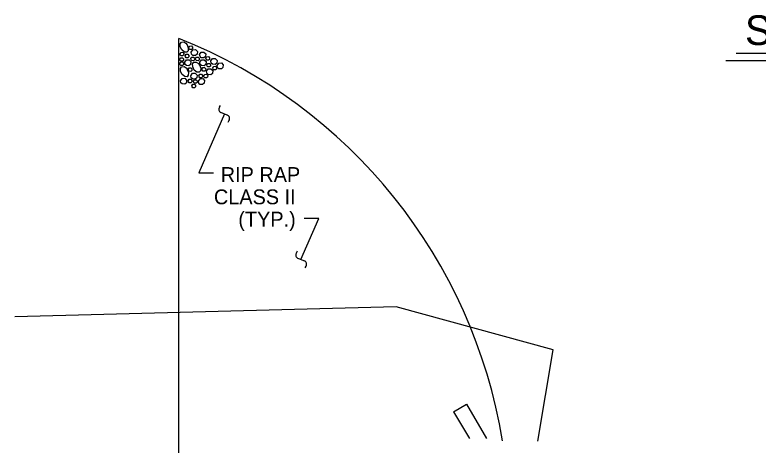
# Model space of a CAD drawing. Extents: x 985 to 1514, y -701 to -21.
# Drawn here: x 1052.9 to 1102.9, y -135.8 to -106.8 of the extents above; entities that cross this region are included whole.
import ezdxf

# ---------------------------------------------------------------- set-up
doc = ezdxf.new("R2010")
doc.units = 0
for name, color, linetype in [('Arrowhead Terminators CELL', 7, 'Continuous'), ('Dimension Lines', 7, 'Continuous'), ('Exist Hydro Stream or Body of Water', 7, 'Continuous'), ('Exist Structure Major Bridge Seam', 7, 'Continuous'), ('Miscellaneous Lines CELL', 7, 'Continuous'), ('Sup Concrete Girder Lines', 7, 'Continuous'), ('Text', 7, 'Continuous'), ('Title Text', 7, 'Continuous')]:
    doc.layers.add(name, color=color, linetype=linetype)

msp = doc.modelspace()

# ---------------------------------------------------------------- linework, layer by layer
at = {"layer": 'Arrowhead Terminators CELL'}
for p, q in [((1066.674, -113.018), (1066.749, -112.892)), ((1067.186, -113.537), (1066.78, -113.361)), ((1067.255, -114.016), (1067.315, -113.924)), ((1071.919, -122.71), (1071.859, -122.802)), ((1071.989, -123.189), (1072.395, -123.364)), ((1072.501, -123.707), (1072.426, -123.834))]:
    msp.add_line(p, q, dxfattribs=at)
for centre, radius, start, end in [((1066.85, -113.154), 0.221, 142.4705, 250.7561), ((1067.114, -113.774), 0.249, 323.4021, 73.201), ((1072.061, -122.951), 0.249, 143.4021, 253.201), ((1072.324, -123.572), 0.221, 322.4705, 70.7561)]:
    msp.add_arc(centre, radius, start, end, dxfattribs=at)
at = {"layer": 'Dimension Lines'}
for p, q in [((1067.013, -113.456), (1065.3, -117.422)), ((1065.3, -117.422), (1066.271, -117.422)), ((1072.162, -123.269), (1073.36, -120.496)), ((1073.36, -120.496), (1072.388, -120.496))]:
    msp.add_line(p, q, dxfattribs=at)
at = {"layer": 'Exist Hydro Stream or Body of Water'}
msp.add_lwpolyline([(1088.115, -135.484), (1089.142, -129.337), (1078.568, -126.457), (1052.905, -127.134)], dxfattribs=at)
at = {"layer": 'Exist Structure Major Bridge Seam'}
for p, q in [((1082.439, -133.508), (1083.301, -133.001)), ((1083.301, -133.001), (1084.655, -135.305)), ((1082.439, -133.508), (1083.505, -135.322))]:
    msp.add_line(p, q, dxfattribs=at)
at = {"layer": 'Miscellaneous Lines CELL'}
for points in [[(1064.499, -108.808), (1064.582, -109.018), (1064.565, -109.211), (1064.478, -109.302), (1064.322, -109.299), (1064.144, -109.16), (1064.037, -108.946), (1064.034, -108.743), (1064.114, -108.63), (1064.276, -108.619), (1064.42, -108.711), (1064.504, -108.817)], [(1064.617, -108.99), (1064.684, -108.895), (1064.792, -108.889), (1064.866, -108.966), (1064.855, -109.074), (1064.789, -109.129), (1064.683, -109.122), (1064.633, -109.073), (1064.617, -108.99)], [(1064.027, -109.419), (1064.094, -109.323), (1064.202, -109.317), (1064.276, -109.395), (1064.266, -109.503), (1064.199, -109.558), (1064.093, -109.551), (1064.043, -109.502), (1064.027, -109.419)], [(1064.374, -109.547), (1064.442, -109.451), (1064.549, -109.445), (1064.624, -109.522), (1064.613, -109.631), (1064.547, -109.686), (1064.441, -109.678), (1064.391, -109.63), (1064.374, -109.547)], [(1064.779, -109.303), (1064.891, -109.144), (1065.07, -109.133), (1065.194, -109.262), (1065.176, -109.443), (1065.066, -109.535), (1064.889, -109.522), (1064.806, -109.442), (1064.779, -109.303)], [(1065.342, -109.466), (1065.454, -109.306), (1065.633, -109.296), (1065.757, -109.425), (1065.739, -109.606), (1065.629, -109.698), (1065.452, -109.685), (1065.369, -109.604), (1065.342, -109.466)], [(1064.017, -109.78), (1064.084, -109.684), (1064.191, -109.678), (1064.266, -109.755), (1064.255, -109.864), (1064.189, -109.919), (1064.083, -109.911), (1064.033, -109.863), (1064.017, -109.78)], [(1064.017, -110.07), (1064.084, -109.974), (1064.191, -109.968), (1064.266, -110.045), (1064.255, -110.154), (1064.189, -110.209), (1064.083, -110.201), (1064.033, -110.153), (1064.017, -110.07)], [(1064.34, -109.987), (1064.452, -109.828), (1064.631, -109.818), (1064.755, -109.946), (1064.737, -110.127), (1064.627, -110.219), (1064.45, -110.206), (1064.367, -110.126), (1064.34, -109.987)], [(1064.76, -109.742), (1064.827, -109.646), (1064.935, -109.64), (1065.009, -109.717), (1064.999, -109.826), (1064.932, -109.881), (1064.826, -109.873), (1064.776, -109.825), (1064.76, -109.742)], [(1065.337, -110.168), (1065.42, -110.377), (1065.404, -110.57), (1065.317, -110.661), (1065.16, -110.659), (1064.983, -110.52), (1064.875, -110.305), (1064.872, -110.103), (1064.953, -109.989), (1065.114, -109.978), (1065.258, -110.07), (1065.342, -110.176)], [(1065.064, -109.742), (1065.131, -109.646), (1065.239, -109.64), (1065.313, -109.717), (1065.303, -109.826), (1065.236, -109.881), (1065.13, -109.873), (1065.08, -109.825), (1065.064, -109.742)], [(1065.359, -109.987), (1065.471, -109.828), (1065.65, -109.818), (1065.774, -109.946), (1065.756, -110.127), (1065.646, -110.219), (1065.469, -110.206), (1065.386, -110.126), (1065.359, -109.987)], [(1065.762, -109.706), (1065.829, -109.61), (1065.936, -109.604), (1066.011, -109.681), (1066, -109.79), (1065.934, -109.845), (1065.828, -109.837), (1065.778, -109.789), (1065.762, -109.706)], [(1065.826, -110.161), (1065.893, -110.066), (1066.001, -110.06), (1066.075, -110.137), (1066.065, -110.245), (1065.998, -110.301), (1065.892, -110.293), (1065.842, -110.245), (1065.826, -110.161)], [(1066.101, -109.898), (1066.214, -109.738), (1066.392, -109.728), (1066.517, -109.857), (1066.499, -110.038), (1066.388, -110.13), (1066.212, -110.117), (1066.129, -110.036), (1066.102, -109.898)], [(1066.517, -110.199), (1066.629, -110.04), (1066.808, -110.03), (1066.933, -110.159), (1066.915, -110.339), (1066.804, -110.431), (1066.627, -110.419), (1066.544, -110.338), (1066.517, -110.199)], [(1064.514, -110.464), (1064.597, -110.674), (1064.58, -110.866), (1064.493, -110.958), (1064.337, -110.955), (1064.159, -110.816), (1064.052, -110.601), (1064.048, -110.399), (1064.129, -110.285), (1064.291, -110.274), (1064.435, -110.367), (1064.519, -110.473)], [(1064.577, -110.463), (1064.644, -110.368), (1064.751, -110.362), (1064.826, -110.439), (1064.815, -110.547), (1064.749, -110.602), (1064.643, -110.595), (1064.593, -110.546), (1064.577, -110.463)], [(1065.501, -110.445), (1065.568, -110.35), (1065.676, -110.344), (1065.75, -110.421), (1065.74, -110.529), (1065.673, -110.584), (1065.567, -110.577), (1065.517, -110.528), (1065.501, -110.445)], [(1065.808, -110.592), (1065.92, -110.432), (1066.099, -110.422), (1066.223, -110.551), (1066.205, -110.732), (1066.094, -110.824), (1065.918, -110.811), (1065.835, -110.73), (1065.808, -110.592)], [(1066.237, -110.357), (1066.304, -110.261), (1066.412, -110.255), (1066.486, -110.332), (1066.475, -110.441), (1066.409, -110.496), (1066.303, -110.488), (1066.253, -110.44), (1066.237, -110.357)], [(1064.055, -111.229), (1064.167, -111.069), (1064.346, -111.059), (1064.47, -111.188), (1064.452, -111.369), (1064.342, -111.461), (1064.165, -111.448), (1064.082, -111.367), (1064.055, -111.229)], [(1064.753, -110.891), (1064.865, -110.731), (1065.044, -110.721), (1065.168, -110.85), (1065.15, -111.031), (1065.039, -111.123), (1064.863, -111.11), (1064.78, -111.029), (1064.753, -110.891)], [(1065.292, -110.893), (1065.36, -110.797), (1065.467, -110.791), (1065.542, -110.869), (1065.531, -110.977), (1065.464, -111.032), (1065.358, -111.025), (1065.309, -110.976), (1065.292, -110.893)], [(1065.637, -110.898), (1065.704, -110.802), (1065.812, -110.796), (1065.886, -110.873), (1065.876, -110.982), (1065.809, -111.037), (1065.703, -111.029), (1065.653, -110.981), (1065.637, -110.898)], [(1064.577, -111.228), (1064.644, -111.133), (1064.751, -111.126), (1064.826, -111.204), (1064.815, -111.312), (1064.749, -111.367), (1064.643, -111.36), (1064.593, -111.311), (1064.577, -111.228)], [(1064.816, -111.566), (1064.883, -111.47), (1064.991, -111.464), (1065.065, -111.541), (1065.055, -111.65), (1064.988, -111.705), (1064.882, -111.697), (1064.832, -111.649), (1064.816, -111.566)], [(1064.931, -111.261), (1064.998, -111.166), (1065.105, -111.16), (1065.18, -111.237), (1065.169, -111.345), (1065.103, -111.401), (1064.997, -111.393), (1064.947, -111.345), (1064.931, -111.261)], [(1065.257, -111.259), (1065.369, -111.099), (1065.548, -111.089), (1065.672, -111.218), (1065.654, -111.399), (1065.544, -111.49), (1065.367, -111.478), (1065.284, -111.397), (1065.257, -111.259)]]:
    msp.add_lwpolyline(points, dxfattribs=at)
at = {"layer": 'Sup Concrete Girder Lines'}
msp.add_line((1063.952, -140.593), (1063.952, -108.386), dxfattribs=at)
msp.add_arc((1050.914, -141.178), 35.289, 9.311, 68.3178, dxfattribs=at)
at = {"layer": 'Title Text'}
for p, q in [((1101.455, -109.363), (1134.037, -109.363)), ((1100.774, -109.863), (1134.812, -109.863))]:
    msp.add_line(p, q, dxfattribs=at)

# ---------------------------------------------------------------- texts
at = {"layer": 'Text'}
for s, p in [('RIP RAP', (1066.763, -118.047)), ('CLASS II', (1066.306, -119.547)), ('(TYP.)', (1067.948, -121.047))]:
    msp.add_text(s, height=1, dxfattribs=at).set_placement(p)
at = {"layer": 'Title Text'}
msp.add_text('SECTION ALONG -L-', height=2, dxfattribs=at).set_placement((1102.055, -108.826))

doc.saveas('drawing.dxf')
